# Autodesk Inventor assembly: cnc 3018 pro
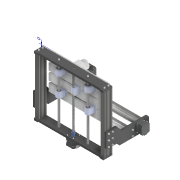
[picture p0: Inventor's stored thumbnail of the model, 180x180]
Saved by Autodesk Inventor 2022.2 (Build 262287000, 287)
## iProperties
Created: 2023-04
Part Number: cnc 3018 pro
Description: STEP AP214
Document SubType Name: Assembly
Designer: 18907419
Sending System: SolidWorks 2023
Preprocessor: SwSTEP 2.0
Title: Baugruppe - Original.STEP
Revision Number: ANY
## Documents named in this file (37)
- C:\Users\18907419\Desktop\cnc 3018\cnc 3018 pro.iam
- C:\Users\18907419\Desktop\cnc 3018\Original - Nutenstein klein M5.ipt
- C:\Users\18907419\Desktop\cnc 3018\Original - Nutenstein M5.ipt
- C:\Users\18907419\Desktop\cnc 3018\Original - Zylinderkopfschraube M4x30.ipt
- C:\Users\18907419\Desktop\cnc 3018\Original - Madenschraube M4x4.ipt
- C:\Users\18907419\Desktop\cnc 3018\Original - Zylinderkopfschraube M3x14.ipt
- C:\Users\18907419\Desktop\cnc 3018\Original - Zylinderkopfschraube M3x20.ipt
- C:\Users\18907419\Desktop\cnc 3018\Original - Zylinderkopfschraube M5x16.ipt
- C:\Users\18907419\Desktop\cnc 3018\Original - Aluminium Profil X.ipt
- C:\Users\18907419\Desktop\cnc 3018\Original - Rahmen X Richtung Y+.ipt
- C:\Users\18907419\Desktop\cnc 3018\Original - Rahmen X Richtung Y-.ipt
- C:\Users\18907419\Desktop\cnc 3018\Original - Aluminium Profil Y.ipt
- C:\Users\18907419\Desktop\cnc 3018\Original - Seitenteil Links.ipt
- C:\Users\18907419\Desktop\cnc 3018\Original - Seitenteil Rechts.ipt
- C:\Users\18907419\Desktop\cnc 3018\Original - Schrittmotor.ipt
- C:\Users\18907419\Desktop\cnc 3018\JST-Steckverbinder-6Pin.ipt
- C:\Users\18907419\Desktop\cnc 3018\Original - Trapezwelle X Achse.ipt
- C:\Users\18907419\Desktop\cnc 3018\Original - Führungswelle Verbinder.ipt
- C:\Users\18907419\Desktop\cnc 3018\Original - KugellagerD16D8H5.ipt
- C:\Users\18907419\Desktop\cnc 3018\Original - T Achse Schrittmotor Träger.ipt
- C:\Users\18907419\Desktop\cnc 3018\Original - Trapezgewindemutter .ipt
- C:\Users\18907419\Desktop\cnc 3018\Original - Trapezgewindemutter Mitnehmer .ipt
- C:\Users\18907419\Desktop\cnc 3018\Original - Trapezgewindemutter Gehäuse.ipt
- C:\Users\18907419\Desktop\cnc 3018\Original - Trapezwelle Y Achse.ipt
- C:\Users\18907419\Desktop\cnc 3018\Original - Spacer Schrittmotor.ipt
- C:\Users\18907419\Desktop\cnc 3018\Original - Trapezwelle Z Achse.ipt
- C:\Users\18907419\Desktop\cnc 3018\Original - Spindelhalter.ipt
- C:\Users\18907419\Desktop\cnc 3018\Original - Kontermutter Spindelhalter.ipt
- C:\Users\18907419\Desktop\cnc 3018\Original - Führungswelle X.ipt
- C:\Users\18907419\Desktop\cnc 3018\Original - LinearlagerA19I10.ipt
- C:\Users\18907419\Desktop\cnc 3018\Original - Linearlager Gehäuse.ipt
- C:\Users\18907419\Desktop\cnc 3018\Original - Führungswelle Y.ipt
- C:\Users\18907419\Desktop\cnc 3018\Original - Führungswelle Z.ipt
- C:\Users\18907419\Desktop\cnc 3018\Original - LinearlagerA15I8.ipt
- C:\Users\18907419\Desktop\cnc 3018\Original - Spindelmotor.ipt
- C:\Users\18907419\Desktop\cnc 3018\Original - Spindelmotor Überwurfmutter.ipt
- C:\Users\18907419\Desktop\cnc 3018\Original - Tisch.ipt
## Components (131 placed, 131 different names)
1. Original - Nutenstein klein M5_1
2. Original - Nutenstein klein M5_2
3. Original - Nutenstein klein M5_3
4. Original - Nutenstein klein M5_4
5. Original - Nutenstein klein M5_5
6. Original - Nutenstein klein M5_6
7. Original - Nutenstein klein M5_7
8. Original - Nutenstein klein M5_8
9. Original - Nutenstein klein M5_9
10. Original - Nutenstein klein M5_10
11. Original - Nutenstein klein M5_11
12. Original - Nutenstein klein M5_12
13. Original - Nutenstein M5_21 — Rotazionale:35, Angolo:7, Angolo:8
14. Original - Nutenstein M5_22 — Rotazionale:34, Angolo:8
15. Original - Zylinderkopfschraube M4x30_23 — Rotazionale:5
16. Original - Madenschraube M4x4_24 — Rigido:4
17. Original - Madenschraube M4x4_27 — Rigido:3
18. Original - Madenschraube M4x4_28
19. Original - Madenschraube M4x4_29
20. Original - Madenschraube M4x4_30
21. Original - Madenschraube M4x4_31
22. Original - Madenschraube M4x4_32 — Rigido:9
23. Original - Madenschraube M4x4_33 — Rigido:8
24. Original - Madenschraube M4x4_34 — Rigido:6
25. Original - Madenschraube M4x4_35 — Rigido:7
26. Original - Zylinderkopfschraube M3x14_36
27. Original - Zylinderkopfschraube M3x14_37
28. Original - Zylinderkopfschraube M3x14_38
29. Original - Zylinderkopfschraube M3x14_39
30. Original - Zylinderkopfschraube M3x14_40
31. Original - Zylinderkopfschraube M3x14_41
32. Original - Zylinderkopfschraube M3x14_42
33. Original - Zylinderkopfschraube M3x14_43
34. Original - Zylinderkopfschraube M3x20_44 — Rotazionale:17
35. Original - Zylinderkopfschraube M3x20_45 — Rotazionale:16
36. Original - Zylinderkopfschraube M3x20_46 — Rotazionale:18
37. Original - Zylinderkopfschraube M3x20_47 — Rotazionale:19
38. Original - Zylinderkopfschraube M5x16_48
39. Original - Zylinderkopfschraube M5x16_49
40. Original - Zylinderkopfschraube M5x16_50
41. Original - Zylinderkopfschraube M5x16_51
42. Original - Zylinderkopfschraube M5x16_52
43. Original - Zylinderkopfschraube M5x16_53
44. Original - Zylinderkopfschraube M5x16_54
45. Original - Zylinderkopfschraube M5x16_55
46. Original - Zylinderkopfschraube M5x16_56
47. Original - Zylinderkopfschraube M5x16_57
48. Original - Zylinderkopfschraube M5x16_58
49. Original - Zylinderkopfschraube M5x16_59
50. Original - Zylinderkopfschraube M5x16_60
51. Original - Zylinderkopfschraube M5x16_61
52. Original - Zylinderkopfschraube M5x16_62
53. Original - Zylinderkopfschraube M5x16_63
54. Original - Zylinderkopfschraube M5x16_64
55. Original - Zylinderkopfschraube M5x16_65
56. Original - Zylinderkopfschraube M5x16_66
57. Original - Zylinderkopfschraube M5x16_67
58. Original - Zylinderkopfschraube M5x16_68
59. Original - Zylinderkopfschraube M5x16_69
60. Original - Zylinderkopfschraube M5x16_70
61. Original - Zylinderkopfschraube M5x16_71
62. Original - Zylinderkopfschraube M5x16_72
63. Original - Zylinderkopfschraube M5x16_73
64. Original - Zylinderkopfschraube M5x16_74
65. Original - Zylinderkopfschraube M5x16_75
66. Original - Zylinderkopfschraube M5x16_76
67. Original - Zylinderkopfschraube M5x16_77
68. Original - Zylinderkopfschraube M5x16_78
69. Original - Zylinderkopfschraube M5x16_79
70. Original - Zylinderkopfschraube M5x16_80
71. Original - Zylinderkopfschraube M5x16_89 — Rotazionale:33
72. Original - Zylinderkopfschraube M5x16_90 — Rotazionale:32
73. Original - Aluminium Profil X_91
74. Original - Aluminium Profil X_92
75. Original - Rahmen X Richtung Y+_93
76. Original - Rahmen X Richtung Y-_94 — Angolo:5, Coincidente:13, Allineato:6, Coincidente:18
77. Original - Aluminium Profil Y_95
78. Original - Aluminium Profil Y_96 — Coincidente:16
79. Original - Seitenteil Links_97 — Coincidente:19
80. Original - Seitenteil Rechts_98
81. Original - Schrittmotor_99
82. Original - Trapezwelle X Achse_101
83. Original - Führungswelle Verbinder_102
84. Original - KugellagerD16D8H5_103
85. Original - T Achse Schrittmotor Träger_104 — Rotazionale:8, Rotazionale:9, Rotazionale:10, Rotazionale:11, Rotazionale:12, Rotazionale:13, Coincidente:2, Angolo:4, Rotazionale:16, Rotazionale:17, Rotazionale:18, Rotazionale:19, Coincidente:3, Rotazionale:21, Rotazionale:22, Rotazionale:23, Rotazionale:24, Rotazionale:25, Coincidente:4, Coincidente:5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
86. Original - Trapezgewindemutter _105 — Rotazionale:26
87. Original - Trapezgewindemutter Mitnehmer _106 — Rotazionale:25
88. Original - Schrittmotor_107 — Rotazionale:36
89. JST-Steckverbinder-6Pin_108
90. Original - Trapezgewindemutter _109 — Rotazionale:30
91. Original - Trapezgewindemutter Mitnehmer _110 — Rotazionale:31, Angolo:6
92. Original - Trapezgewindemutter Gehäuse_111 — Coincidente:10, Allineato:3, Allineato:4, Angolo:5, Rotazionale:30, Rotazionale:31, Angolo:6, Rotazionale:32, Rotazionale:33, Rotazionale:34, Rotazionale:35, Angolo:7, Coincidente:17
93. Original - Trapezwelle Y Achse_112 — Coincidente:10, Coincidente:13, Allineato:6
94. Original - Führungswelle Verbinder_113 — Rotazionale:36, Rigido:6, Rigido:7, Rigido:8, Rigido:9
95. Original - KugellagerD16D8H5_114
96. Original - Schrittmotor_115 — Coincidente:2, Rotazionale:14, Angolo:4, Rotazionale:15
97. Original - Spacer Schrittmotor_116 — Rotazionale:12
98. Original - Spacer Schrittmotor_117 — Rotazionale:10
99. Original - Spacer Schrittmotor_118 — Rotazionale:11, Rotazionale:14
100. Original - Spacer Schrittmotor_119 — Rotazionale:13
101. Original - Trapezwelle Z Achse_121 — Coincidente:3, Rotazionale:20
102. Original - Führungswelle Verbinder_122 — Rotazionale:15, Rigido:3, Rigido:4, Rotazionale:20
103. Original - Spindelhalter_123 — Coincidente:1, Allineato:1, Angolo:1, Rotazionale:1, Rotazionale:2, Rotazionale:3, Rotazionale:4, Rotazionale:5, Rotazionale:6, Angolo:2, Rotazionale:7, Angolo:3, Rigido:2, Coincidente:20
104. Original - Kontermutter Spindelhalter_124 — Rotazionale:6, Angolo:2
105. Original - Trapezgewindemutter _125 — Rigido:2
106. Original - Trapezgewindemutter Mitnehmer _126 — Rotazionale:7, Angolo:3
107. Original - Führungswelle X_127 — Coincidente:4
108. Original - Führungswelle X_128 — Coincidente:5
109. Original - LinearlagerA19I10_129 — Rotazionale:22
110. Original - LinearlagerA19I10_130 — Rotazionale:21
111. Original - LinearlagerA19I10_131 — Rotazionale:23
112. Original - LinearlagerA19I10_132 — Rotazionale:24
113. Original - Linearlager Gehäuse_133 — Coincidente:11, Rigido:5, Allineato:5, Allineato:8
114. Original - LinearlagerA19I10_134 — Rigido:5
115. Original - Linearlager Gehäuse_135 — Coincidente:11, Coincidente:12, Rotazionale:29, Allineato:4, Allineato:5, Allineato:7
116. Original - LinearlagerA19I10_136 — Rotazionale:29
117. Original - Linearlager Gehäuse_137 — Coincidente:9, Rotazionale:28, Allineato:2, Allineato:3, Allineato:8, Coincidente:14, Coincidente:15, Allineato:9, Coincidente:17
118. Original - LinearlagerA19I10_138 — Rotazionale:28
119. Original - Linearlager Gehäuse_139 — Rotazionale:27, Coincidente:8, Allineato:2, Allineato:7, Coincidente:14
120. Original - LinearlagerA19I10_140 — Rotazionale:27
121. Original - Führungswelle Y_141 — Coincidente:8, Coincidente:9
122. Original - Führungswelle Y_142 — Coincidente:12
123. Original - Führungswelle Z_143 — Rotazionale:8, Coincidente:7
124. Original - Führungswelle Z_144 — Rotazionale:9, Coincidente:6
125. Original - LinearlagerA15I8_145 — Rotazionale:2
126. Original - LinearlagerA15I8_146 — Rotazionale:4
127. Original - LinearlagerA15I8_147 — Rotazionale:1, Coincidente:6
128. Original - LinearlagerA15I8_148 — Rotazionale:3, Coincidente:7
129. Original - Spindelmotor_149 — Rigido:1, Coincidente:1, Allineato:1, Angolo:1
130. Original - Spindelmotor Überwurfmutter_152 — Rigido:1
131. Original - Tisch_153 — Coincidente:15, Coincidente:16, Allineato:9, Coincidente:18
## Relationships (82: RevoluteJoint 36, Mate 20, WeldJoint 9, Flush 9, Angle 8)
- Rigido:1 [WeldJoint]: Original - Spindelmotor_149 ↔ Original - Spindelmotor Überwurfmutter_152
- Coincidente:1 [Mate]: Original - Spindelhalter_123 ↔ Original - Spindelmotor_149
- Allineato:1 [Flush]: Original - Spindelhalter_123 ↔ Original - Spindelmotor_149
- Angolo:1 [Angle]: Original - Spindelhalter_123 ↔ Original - Spindelmotor_149
- Rotazionale:1 [RevoluteJoint]: Original - Spindelhalter_123 ↔ Original - LinearlagerA15I8_147
- Rotazionale:2 [RevoluteJoint]: Original - Spindelhalter_123 ↔ Original - LinearlagerA15I8_145
- Rotazionale:3 [RevoluteJoint]: Original - Spindelhalter_123 ↔ Original - LinearlagerA15I8_148
- Rotazionale:4 [RevoluteJoint]: Original - Spindelhalter_123 ↔ Original - LinearlagerA15I8_146
- Rotazionale:5 [RevoluteJoint]: Original - Zylinderkopfschraube M4x30_23 ↔ Original - Spindelhalter_123
- Rotazionale:6 [RevoluteJoint]: Original - Spindelhalter_123 ↔ Original - Kontermutter Spindelhalter_124
- Angolo:2 [Angle]: Original - Spindelhalter_123 ↔ Original - Kontermutter Spindelhalter_124
- Rotazionale:7 [RevoluteJoint]: Original - Spindelhalter_123 ↔ Original - Trapezgewindemutter Mitnehmer _126
- Angolo:3 [Angle]: Original - Spindelhalter_123 ↔ Original - Trapezgewindemutter Mitnehmer _126
- Rigido:2 [WeldJoint]: Original - Spindelhalter_123 ↔ Original - Trapezgewindemutter _125
- Rotazionale:8 [RevoluteJoint]: Original - T Achse Schrittmotor Träger_104 ↔ Original - Führungswelle Z_143
- Rotazionale:9 [RevoluteJoint]: Original - T Achse Schrittmotor Träger_104 ↔ Original - Führungswelle Z_144
- Rotazionale:10 [RevoluteJoint]: Original - T Achse Schrittmotor Träger_104 ↔ Original - Spacer Schrittmotor_117
- Rotazionale:11 [RevoluteJoint]: Original - T Achse Schrittmotor Träger_104 ↔ Original - Spacer Schrittmotor_118
- Rotazionale:12 [RevoluteJoint]: Original - T Achse Schrittmotor Träger_104 ↔ Original - Spacer Schrittmotor_116
- Rotazionale:13 [RevoluteJoint]: Original - T Achse Schrittmotor Träger_104 ↔ Original - Spacer Schrittmotor_119
- Coincidente:2 [Mate]: Original - T Achse Schrittmotor Träger_104 ↔ Original - Schrittmotor_115
- Rotazionale:14 [RevoluteJoint]: Original - Schrittmotor_115 ↔ Original - Spacer Schrittmotor_118
- Angolo:4 [Angle]: Original - T Achse Schrittmotor Träger_104 ↔ Original - Schrittmotor_115
- Rotazionale:15 [RevoluteJoint]: Original - Schrittmotor_115 ↔ Original - Führungswelle Verbinder_122
- Rigido:3 [WeldJoint]: Original - Madenschraube M4x4_27 ↔ Original - Führungswelle Verbinder_122
- Rigido:4 [WeldJoint]: Original - Madenschraube M4x4_24 ↔ Original - Führungswelle Verbinder_122
- Rotazionale:16 [RevoluteJoint]: Original - Zylinderkopfschraube M3x20_45 ↔ Original - T Achse Schrittmotor Träger_104
- Rotazionale:17 [RevoluteJoint]: Original - Zylinderkopfschraube M3x20_44 ↔ Original - T Achse Schrittmotor Träger_104
- Rotazionale:18 [RevoluteJoint]: Original - Zylinderkopfschraube M3x20_46 ↔ Original - T Achse Schrittmotor Träger_104
- Rotazionale:19 [RevoluteJoint]: Original - Zylinderkopfschraube M3x20_47 ↔ Original - T Achse Schrittmotor Träger_104
- Coincidente:3 [Mate]: Original - T Achse Schrittmotor Träger_104 ↔ Original - Trapezwelle Z Achse_121
- Rotazionale:20 [RevoluteJoint]: Original - Trapezwelle Z Achse_121 ↔ Original - Führungswelle Verbinder_122
- Rotazionale:21 [RevoluteJoint]: Original - T Achse Schrittmotor Träger_104 ↔ Original - LinearlagerA19I10_130
- Rotazionale:22 [RevoluteJoint]: Original - T Achse Schrittmotor Träger_104 ↔ Original - LinearlagerA19I10_129
- Rotazionale:23 [RevoluteJoint]: Original - T Achse Schrittmotor Träger_104 ↔ Original - LinearlagerA19I10_131
- Rotazionale:24 [RevoluteJoint]: Original - T Achse Schrittmotor Träger_104 ↔ Original - LinearlagerA19I10_132
- Rotazionale:25 [RevoluteJoint]: Original - T Achse Schrittmotor Träger_104 ↔ Original - Trapezgewindemutter Mitnehmer _106
- Coincidente:4 [Mate]: Original - T Achse Schrittmotor Träger_104 ↔ Original - Führungswelle X_127
- Coincidente:5 [Mate]: Original - T Achse Schrittmotor Träger_104 ↔ Original - Führungswelle X_128
- Rotazionale:26 [RevoluteJoint]: Original - T Achse Schrittmotor Träger_104 ↔ Original - Trapezgewindemutter _105
- Coincidente:6 [Mate]: Original - Führungswelle Z_144 ↔ Original - LinearlagerA15I8_147
- Coincidente:7 [Mate]: Original - Führungswelle Z_143 ↔ Original - LinearlagerA15I8_148
- Rotazionale:27 [RevoluteJoint]: Original - Linearlager Gehäuse_139 ↔ Original - LinearlagerA19I10_140
- Coincidente:8 [Mate]: Original - Linearlager Gehäuse_139 ↔ Original - Führungswelle Y_141
- Coincidente:9 [Mate]: Original - Linearlager Gehäuse_137 ↔ Original - Führungswelle Y_141
- Coincidente:10 [Mate]: Original - Trapezgewindemutter Gehäuse_111 ↔ Original - Trapezwelle Y Achse_112
- Coincidente:11 [Mate]: Original - Linearlager Gehäuse_133 ↔ Original - Linearlager Gehäuse_135
- Coincidente:12 [Mate]: Original - Linearlager Gehäuse_135 ↔ Original - Führungswelle Y_142
- Rotazionale:28 [RevoluteJoint]: Original - Linearlager Gehäuse_137 ↔ Original - LinearlagerA19I10_138
- Rigido:5 [WeldJoint]: Original - Linearlager Gehäuse_133 ↔ Original - LinearlagerA19I10_134
- Rotazionale:29 [RevoluteJoint]: Original - Linearlager Gehäuse_135 ↔ Original - LinearlagerA19I10_136
- Allineato:2 [Flush]: Original - Linearlager Gehäuse_137 ↔ Original - Linearlager Gehäuse_139
- Allineato:3 [Flush]: Original - Trapezgewindemutter Gehäuse_111 ↔ Original - Linearlager Gehäuse_137
- Allineato:4 [Flush]: Original - Trapezgewindemutter Gehäuse_111 ↔ Original - Linearlager Gehäuse_135
- Allineato:5 [Flush]: Original - Linearlager Gehäuse_133 ↔ Original - Linearlager Gehäuse_135
- Angolo:5 [Angle]: Original - Rahmen X Richtung Y-_94 ↔ Original - Trapezgewindemutter Gehäuse_111
- Coincidente:13 [Mate]: Original - Rahmen X Richtung Y-_94 ↔ Original - Trapezwelle Y Achse_112
- Allineato:6 [Flush]: Original - Rahmen X Richtung Y-_94 ↔ Original - Trapezwelle Y Achse_112
- Rotazionale:30 [RevoluteJoint]: Original - Trapezgewindemutter _109 ↔ Original - Trapezgewindemutter Gehäuse_111
- Rotazionale:31 [RevoluteJoint]: Original - Trapezgewindemutter Mitnehmer _110 ↔ Original - Trapezgewindemutter Gehäuse_111
- Angolo:6 [Angle]: Original - Trapezgewindemutter Mitnehmer _110 ↔ Original - Trapezgewindemutter Gehäuse_111
- Rotazionale:32 [RevoluteJoint]: Original - Zylinderkopfschraube M5x16_90 ↔ Original - Trapezgewindemutter Gehäuse_111
- Rotazionale:33 [RevoluteJoint]: Original - Zylinderkopfschraube M5x16_89 ↔ Original - Trapezgewindemutter Gehäuse_111
- Rotazionale:34 [RevoluteJoint]: Original - Nutenstein M5_22 ↔ Original - Trapezgewindemutter Gehäuse_111
- Rotazionale:35 [RevoluteJoint]: Original - Nutenstein M5_21 ↔ Original - Trapezgewindemutter Gehäuse_111
- Angolo:7 [Angle]: Original - Nutenstein M5_21 ↔ Original - Trapezgewindemutter Gehäuse_111
- Angolo:8 [Angle]: Original - Nutenstein M5_21 ↔ Original - Nutenstein M5_22
- Rotazionale:36 [RevoluteJoint]: Original - Schrittmotor_107 ↔ Original - Führungswelle Verbinder_113
- Rigido:6 [WeldJoint]: Original - Madenschraube M4x4_34 ↔ Original - Führungswelle Verbinder_113
- Rigido:7 [WeldJoint]: Original - Madenschraube M4x4_35 ↔ Original - Führungswelle Verbinder_113
- Rigido:8 [WeldJoint]: Original - Madenschraube M4x4_33 ↔ Original - Führungswelle Verbinder_113
- Rigido:9 [WeldJoint]: Original - Madenschraube M4x4_32 ↔ Original - Führungswelle Verbinder_113
- Allineato:7 [Flush]: Original - Linearlager Gehäuse_135 ↔ Original - Linearlager Gehäuse_139
- Allineato:8 [Flush]: Original - Linearlager Gehäuse_133 ↔ Original - Linearlager Gehäuse_137
- Coincidente:14 [Mate]: Original - Linearlager Gehäuse_137 ↔ Original - Linearlager Gehäuse_139
- Coincidente:15 [Mate]: Original - Linearlager Gehäuse_137 ↔ Original - Tisch_153
- Coincidente:16 [Mate]: Original - Aluminium Profil Y_96 ↔ Original - Tisch_153
- Allineato:9 [Flush]: Original - Linearlager Gehäuse_137 ↔ Original - Tisch_153
- Coincidente:17 [Mate]: Original - Trapezgewindemutter Gehäuse_111 ↔ Original - Linearlager Gehäuse_137
- Coincidente:18 [Mate]: Original - Rahmen X Richtung Y-_94 ↔ Original - Tisch_153
- Coincidente:19 [Mate]: Original - Seitenteil Links_97 ↔ Original - T Achse Schrittmotor Träger_104
- Coincidente:20 [Mate]: Original - T Achse Schrittmotor Träger_104 ↔ Original - Spindelhalter_123
